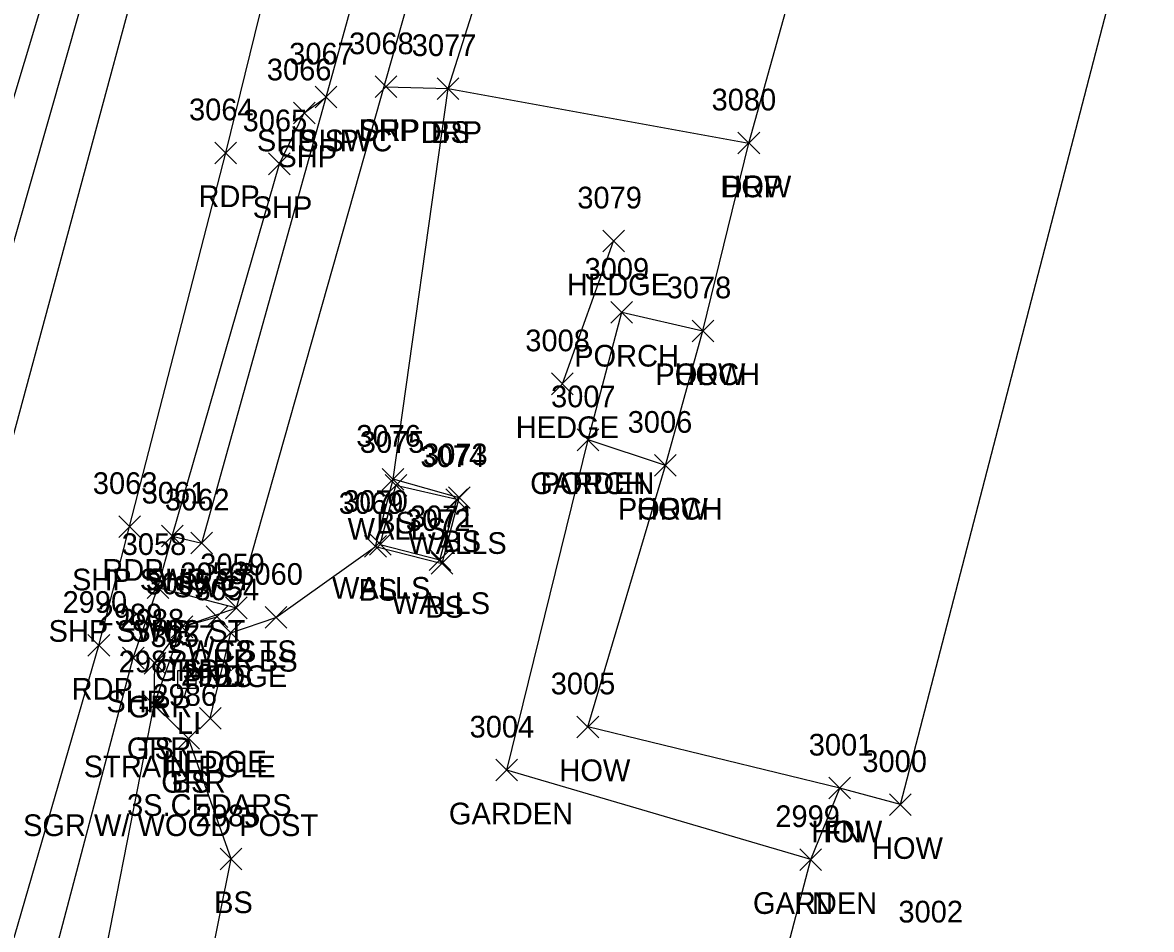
# Model space of a CAD drawing. Extents: x 1477930 to 1480780, y 774090 to 784647.
# Drawn here: x 1479566.7 to 1479670.7, y 775167.1 to 775250.7 of the extents above; entities that cross this region are included whole.
import ezdxf

# ---------------------------------------------------------------- set-up
doc = ezdxf.new("R2010")
doc.units = 0
for name, color, linetype in [('L_A', 7, 'Continuous'), ('L_C', 7, 'Continuous'), ('L_I', 7, 'Continuous'), ('L_TIC', 7, 'Continuous'), ('LAHR', 7, 'Continuous'), ('LAPB', 7, 'Continuous'), ('LBC', 7, 'Continuous'), ('LBF', 7, 'Continuous'), ('LELB', 7, 'Continuous'), ('LFNC', 7, 'Continuous'), ('LWS', 7, 'Continuous'), ('P_A', 7, 'Continuous'), ('P_I', 7, 'Continuous'), ('P_TIC', 7, 'Continuous'), ('PET', 7, 'Continuous'), ('PRC', 7, 'Continuous'), ('PSP', 7, 'Continuous'), ('R_A', 7, 'Continuous'), ('R_I', 7, 'Continuous'), ('R_TIC', 7, 'Continuous'), ('RDP', 7, 'Continuous'), ('RGR', 7, 'Continuous'), ('RSW', 7, 'Continuous'), ('U_A', 7, 'Continuous'), ('U_C', 7, 'Continuous'), ('U_I', 7, 'Continuous'), ('ULP', 7, 'Continuous')]:
    doc.layers.add(name, color=color, linetype=linetype)

msp = doc.modelspace()

# ---------------------------------------------------------------- linework, layer by layer
at = {"layer": 'L_TIC'}
for points in [[(1479604.91, 775243.6), (1479606.91, 775245.6)], [(1479606.91, 775243.6), (1479604.91, 775245.6)], [(1479632.62, 775238.59), (1479634.62, 775240.59)], [(1479634.62, 775238.59), (1479632.62, 775240.59)], [(1479620.16, 775229.56), (1479622.16, 775231.56)], [(1479622.16, 775229.56), (1479620.16, 775231.56)], [(1479620.91, 775222.99), (1479622.91, 775224.99)], [(1479622.91, 775222.99), (1479620.91, 775224.99)], [(1479628.39, 775221.28), (1479630.39, 775223.28)], [(1479630.39, 775221.28), (1479628.39, 775223.28)], [(1479628.39, 775221.28), (1479630.39, 775223.28)], [(1479630.39, 775221.28), (1479628.39, 775223.28)], [(1479615.45, 775216.4), (1479617.45, 775218.4)], [(1479617.45, 775216.4), (1479615.45, 775218.4)], [(1479617.81, 775211.24), (1479619.81, 775213.24)], [(1479619.81, 775211.24), (1479617.81, 775213.24)], [(1479617.81, 775211.24), (1479619.81, 775213.24)], [(1479619.81, 775211.24), (1479617.81, 775213.24)], [(1479624.93, 775208.89), (1479626.93, 775210.89)], [(1479626.93, 775208.89), (1479624.93, 775210.89)], [(1479624.93, 775208.89), (1479626.93, 775210.89)], [(1479626.93, 775208.89), (1479624.93, 775210.89)], [(1479599.85, 775207.61), (1479601.85, 775209.61)], [(1479601.85, 775207.61), (1479599.85, 775209.61)], [(1479599.85, 775207.61), (1479601.85, 775209.61)], [(1479601.85, 775207.61), (1479599.85, 775209.61)], [(1479600.11, 775207.04), (1479602.11, 775209.04)], [(1479602.11, 775207.04), (1479600.11, 775209.04)], [(1479600.11, 775207.04), (1479602.11, 775209.04)], [(1479602.11, 775207.04), (1479600.11, 775209.04)], [(1479605.71, 775205.73), (1479607.71, 775207.73)], [(1479607.71, 775205.73), (1479605.71, 775207.73)], [(1479605.94, 775205.9), (1479607.94, 775207.9)], [(1479607.94, 775205.9), (1479605.94, 775207.9)], [(1479598.23, 775201.42), (1479600.23, 775203.42)], [(1479600.23, 775201.42), (1479598.23, 775203.42)], [(1479598.23, 775201.42), (1479600.23, 775203.42)], [(1479600.23, 775201.42), (1479598.23, 775203.42)], [(1479598.67, 775201.6), (1479600.67, 775203.6)], [(1479600.67, 775201.6), (1479598.67, 775203.6)], [(1479598.67, 775201.6), (1479600.67, 775203.6)], [(1479600.67, 775201.6), (1479598.67, 775203.6)], [(1479604.17, 775200.19), (1479606.17, 775202.19)], [(1479606.17, 775200.19), (1479604.17, 775202.19)], [(1479604.36, 775199.85), (1479606.36, 775201.85)], [(1479606.36, 775199.85), (1479604.36, 775201.85)], [(1479585.42, 775195.76), (1479587.42, 775197.76)], [(1479587.42, 775195.76), (1479585.42, 775197.76)], [(1479589.06, 775194.88), (1479591.06, 775196.88)], [(1479591.06, 775194.88), (1479589.06, 775196.88)], [(1479580.4, 775194.01), (1479582.4, 775196.01)], [(1479582.4, 775194.01), (1479580.4, 775196.01)], [(1479584.89, 775193.46), (1479586.89, 775195.46)], [(1479586.89, 775193.46), (1479584.89, 775195.46)], [(1479584.89, 775193.46), (1479586.89, 775195.46)], [(1479586.89, 775193.46), (1479584.89, 775195.46)], [(1479577.83, 775186.82), (1479579.83, 775188.82)], [(1479579.83, 775186.82), (1479577.83, 775188.82)], [(1479583, 775185.59), (1479585, 775187.59)], [(1479585, 775185.59), (1479583, 775187.59)], [(1479617.79, 775184.79), (1479619.79, 775186.79)], [(1479619.79, 775184.79), (1479617.79, 775186.79)], [(1479581, 775183.73), (1479583, 775185.73)], [(1479583, 775183.73), (1479581, 775185.73)], [(1479610.32, 775180.81), (1479612.32, 775182.81)], [(1479612.32, 775180.81), (1479610.32, 775182.81)], [(1479640.99, 775179.15), (1479642.99, 775181.15)], [(1479642.99, 775179.15), (1479640.99, 775181.15)], [(1479640.99, 775179.15), (1479642.99, 775181.15)], [(1479642.99, 775179.15), (1479640.99, 775181.15)], [(1479646.59, 775177.63), (1479648.59, 775179.63)], [(1479648.59, 775177.63), (1479646.59, 775179.63)], [(1479646.59, 775177.63), (1479648.59, 775179.63)], [(1479648.59, 775177.63), (1479646.59, 775179.63)], [(1479584.92, 775172.63), (1479586.92, 775174.63)], [(1479586.92, 775172.63), (1479584.92, 775174.63)], [(1479638.33, 775172.56), (1479640.33, 775174.56)], [(1479640.33, 775172.56), (1479638.33, 775174.56)], [(1479638.33, 775172.56), (1479640.33, 775174.56)], [(1479640.33, 775172.56), (1479638.33, 775174.56)]]:
    msp.add_lwpolyline(points, dxfattribs=at)
at = {"layer": 'LAHR'}
for points in [[(1479616.45, 775217.4), (1479621.16, 775230.56)], [(1479584, 775186.59), (1479585.89, 775194.46)]]:
    msp.add_lwpolyline(points, dxfattribs=at)
at = {"layer": 'LAPB'}
msp.add_lwpolyline([(1479639.33, 775173.56), (1479611.32, 775181.81), (1479618.81, 775212.24)], dxfattribs=at)
at = {"layer": 'LBC'}
for points in [[(1479647.59, 775178.63), (1479641.99, 775180.15), (1479618.79, 775185.79), (1479625.93, 775209.89), (1479629.39, 775222.28), (1479633.62, 775239.59), (1479640.38, 775263.77), (1479667.82, 775256.6)], [(1479647.59, 775178.63), (1479667.82, 775256.6)]]:
    msp.add_lwpolyline(points, dxfattribs=at)
at = {"layer": 'LBF'}
msp.add_lwpolyline([(1479625.93, 775209.89), (1479618.81, 775212.24), (1479621.91, 775223.99), (1479629.39, 775222.28)], dxfattribs=at)
at = {"layer": 'LELB'}
for points in [[(1479585.89, 775194.46), (1479590.06, 775195.88), (1479599.23, 775202.42), (1479600.85, 775208.61), (1479605.91, 775244.6), (1479612.99, 775266.82), (1479623.15, 775296.78)], [(1479599.23, 775202.42), (1479605.36, 775200.85), (1479606.94, 775206.9), (1479600.85, 775208.61)], [(1479562.22, 775125.25), (1479572.92, 775157.6), (1479578.83, 775187.82), (1479581.4, 775195.01), (1479586.42, 775196.76)], [(1479495.75, 774910.51), (1479499.97, 774927.51), (1479504.38, 774948.16), (1479520.64, 774990.18), (1479525.58, 774996.15), (1479529.8, 774996.91), (1479531.37, 775007.34), (1479547.96, 775049.91), (1479566.92, 775099.68), (1479572.67, 775121.86), (1479581.47, 775151.49), (1479585.92, 775173.63), (1479582, 775184.73)]]:
    msp.add_lwpolyline(points, dxfattribs=at)
at = {"layer": 'LFNC'}
msp.add_lwpolyline([(1479670.71, 775144.89), (1479666.14, 775128.07), (1479629.86, 775137.61), (1479639.33, 775173.56), (1479641.99, 775180.15)], dxfattribs=at)
at = {"layer": 'LWS'}
for points in [[(1479599.67, 775202.6), (1479605.17, 775201.19), (1479606.71, 775206.73), (1479601.11, 775208.04)], [(1479599.67, 775202.6), (1479601.11, 775208.04)]]:
    msp.add_lwpolyline(points, dxfattribs=at)
at = {"layer": 'P_TIC'}
for points in [[(1479599.19, 775243.77), (1479601.19, 775245.77)], [(1479601.19, 775243.77), (1479599.19, 775245.77)], [(1479593.67, 775242.82), (1479595.67, 775244.82)], [(1479595.67, 775242.82), (1479593.67, 775244.82)], [(1479591.66, 775241.36), (1479593.66, 775243.36)], [(1479593.66, 775241.36), (1479591.66, 775243.36)], [(1479584.43, 775237.68), (1479586.43, 775239.68)], [(1479586.43, 775237.68), (1479584.43, 775239.68)], [(1479589.38, 775236.67), (1479591.38, 775238.67)], [(1479591.38, 775236.67), (1479589.38, 775238.67)], [(1479575.58, 775203.25), (1479577.58, 775205.25)], [(1479577.58, 775203.25), (1479575.58, 775205.25)], [(1479579.51, 775202.37), (1479581.51, 775204.37)], [(1479581.51, 775202.37), (1479579.51, 775204.37)], [(1479578.19, 775197.63), (1479580.19, 775199.63)], [(1479580.19, 775197.63), (1479578.19, 775199.63)], [(1479572.74, 775192.3), (1479574.74, 775194.3)], [(1479574.74, 775192.3), (1479572.74, 775194.3)], [(1479575.91, 775191.14), (1479577.91, 775193.14)], [(1479577.91, 775191.14), (1479575.91, 775193.14)]]:
    msp.add_lwpolyline(points, dxfattribs=at)
at = {"layer": 'PET'}
msp.add_lwpolyline([(1479231.31, 774636.06), (1479272.54, 774672.78), (1479302.99, 774702.6), (1479344.22, 774746.86), (1479373.44, 774780.01), (1479405.23, 774818.27), (1479428.23, 774848.68), (1479447.93, 774875.75), (1479460.71, 774894.51), (1479479.69, 774925.18), (1479480.31, 774927.38), (1479493.45, 774951.2), (1479514.74, 775006.53), (1479531.7, 775055.13), (1479548.14, 775106.72), (1479553.83, 775125.43), (1479564.45, 775161.29), (1479573.74, 775193.3), (1479576.58, 775204.25), (1479585.43, 775238.68), (1479593.96, 775273.34), (1479599.4, 775295.6)], dxfattribs=at)
at = {"layer": 'PRC'}
for points in [[(1479587.72, 775307.65), (1479575.01, 775262.49), (1479563.12, 775220.83), (1479548.57, 775168.37), (1479533.5, 775112.54), (1479513.76, 775053.7)], [(1479430.01, 774890.62), (1479468.91, 774957.83), (1479493.21, 775011.92), (1479503.06, 775052.08), (1479530.4, 775123.25), (1479541.54, 775166.06), (1479555.58, 775209.55), (1479571.78, 775263.31), (1479582.9, 775300.17)], [(1479438.76, 774885), (1479466.69, 774929.85), (1479479.06, 774955.89), (1479501.08, 775005.62), (1479520.94, 775059.64), (1479540.23, 775118.92), (1479552.22, 775163.96), (1479564.07, 775206.06), (1479578.9, 775260.88), (1479588.27, 775297.78)]]:
    msp.add_lwpolyline(points, dxfattribs=at)
at = {"layer": 'PSP'}
msp.add_lwpolyline([(1479441.63, 774858.96), (1479460.29, 774885.01), (1479481.52, 774912.36), (1479488.61, 774932.58), (1479495.59, 774950.17), (1479517.9, 775005.3), (1479535.63, 775053.88), (1479551.95, 775105.38), (1479558.13, 775123.89), (1479568.29, 775159.47), (1479576.91, 775192.14), (1479579.19, 775198.63), (1479580.51, 775203.37), (1479590.38, 775237.67), (1479592.66, 775242.36), (1479594.67, 775243.82)], dxfattribs=at)
at = {"layer": 'R_TIC'}
for points in [[(1479599.19, 775243.77), (1479601.19, 775245.77)], [(1479601.19, 775243.77), (1479599.19, 775245.77)], [(1479604.91, 775243.6), (1479606.91, 775245.6)], [(1479606.91, 775243.6), (1479604.91, 775245.6)], [(1479593.67, 775242.82), (1479595.67, 775244.82)], [(1479595.67, 775242.82), (1479593.67, 775244.82)], [(1479632.62, 775238.59), (1479634.62, 775240.59)], [(1479634.62, 775238.59), (1479632.62, 775240.59)], [(1479579.51, 775202.37), (1479581.51, 775204.37)], [(1479581.51, 775202.37), (1479579.51, 775204.37)], [(1479582.22, 775201.73), (1479584.22, 775203.73)], [(1479584.22, 775201.73), (1479582.22, 775203.73)], [(1479578.19, 775197.63), (1479580.19, 775199.63)], [(1479580.19, 775197.63), (1479578.19, 775199.63)], [(1479585.42, 775195.76), (1479587.42, 775197.76)], [(1479587.42, 775195.76), (1479585.42, 775197.76)], [(1479583.64, 775194.94), (1479585.64, 775196.94)], [(1479585.64, 775194.94), (1479583.64, 775196.94)], [(1479580.4, 775194.01), (1479582.4, 775196.01)], [(1479582.4, 775194.01), (1479580.4, 775196.01)], [(1479577.91, 775190.66), (1479579.91, 775192.66)], [(1479579.91, 775190.66), (1479577.91, 775192.66)], [(1479577.83, 775186.82), (1479579.83, 775188.82)], [(1479579.83, 775186.82), (1479577.83, 775188.82)], [(1479581, 775183.73), (1479583, 775185.73)], [(1479583, 775183.73), (1479581, 775185.73)]]:
    msp.add_lwpolyline(points, dxfattribs=at)
at = {"layer": 'RDP'}
msp.add_lwpolyline([(1479600.19, 775244.77), (1479605.91, 775244.6), (1479633.62, 775239.59)], dxfattribs=at)
at = {"layer": 'RGR'}
msp.add_lwpolyline([(1479582, 775184.73), (1479578.83, 775187.82), (1479578.91, 775191.66), (1479581.4, 775195.01), (1479584.64, 775195.94)], dxfattribs=at)
at = {"layer": 'RSW'}
for points in [[(1479580.51, 775203.37), (1479583.22, 775202.73), (1479594.67, 775243.82), (1479602.39, 775271.66), (1479608.81, 775294.92)], [(1479579.19, 775198.63), (1479586.42, 775196.76), (1479607.11, 775269.89), (1479613.43, 775293.13)]]:
    msp.add_lwpolyline(points, dxfattribs=at)
at = {"layer": 'ULP'}
for p, q in [((1479581.01, 775189.32), (1479581.01, 775190.98)), ((1479581.01, 775190.98), (1479582.68, 775190.98)), ((1479582.01, 775191.82), (1479581.84, 775190.98)), ((1479582.68, 775190.98), (1479582.68, 775189.32)), ((1479581.84, 775190.15), (1479581.84, 775190.15)), ((1479582.68, 775189.32), (1479581.01, 775189.32)), ((1479581.59, 775188.48), (1479581.84, 775189.32))]:
    msp.add_line(p, q, dxfattribs=at)

# ---------------------------------------------------------------- texts
at = {"layer": 'L_A'}
for s, p in [('BS', (1479604.35, 775239.6)), ('HOW', (1479631, 775234.59)), ('HEDGE', (1479616.86, 775225.56)), ('PORCH', (1479617.53, 775218.99)), ('PORCH', (1479625.01, 775217.28)), ('HOW', (1479626.77, 775217.28)), ('HEDGE', (1479612.15, 775212.4)), ('GARDEN', (1479613.48, 775207.24)), ('PORCH', (1479614.44, 775207.24)), ('PORCH', (1479621.55, 775204.89)), ('HOW', (1479623.32, 775204.89)), ('BS', (1479599.29, 775203.61)), ('BS', (1479599.29, 775203.61)), ('WALLS', (1479596.66, 775203.04)), ('WALLS', (1479596.66, 775203.04)), ('WALLS', (1479602.25, 775201.73)), ('BS', (1479605.39, 775201.9)), ('WALLS', (1479595.22, 775197.6)), ('WALLS', (1479595.22, 775197.6)), ('BS', (1479597.67, 775197.42)), ('BS', (1479597.67, 775197.42)), ('WALLS', (1479600.72, 775196.19)), ('BS', (1479603.8, 775195.85)), ('TS', (1479584.83, 775191.76)), ('TS', (1479579.81, 775190.01)), ('BS', (1479588.5, 775190.88)), ('HEDGE', (1479581.59, 775189.46)), ('BS', (1479584.33, 775189.46)), ('TS', (1479577.24, 775182.82)), ('HEDGE', (1479579.7, 775181.59)), ('HOW', (1479616.17, 775180.79)), ('BS', (1479580.44, 775179.73)), ('GARDEN', (1479605.99, 775176.81)), ('HOW', (1479639.38, 775175.15)), ('FN', (1479640.47, 775175.15)), ('HOW', (1479644.97, 775173.63)), ('HOW', (1479644.97, 775173.63)), ('BS', (1479584.36, 775168.63)), ('GARDEN', (1479634, 775168.56)), ('FN', (1479637.81, 775168.56))]:
    msp.add_text(s, height=2, dxfattribs=at).set_placement(p)
at = {"layer": 'L_C'}
for s, p in [('3S.CEDARS', (1479576.34, 775177.59)), ('SGR W/ WOOD POST', (1479566.76, 775175.73))]:
    msp.add_text(s, height=2, dxfattribs=at).set_placement(p)
at = {"layer": 'L_I'}
for s, p in [('3077', (1479602.57, 775247.6)), ('3080', (1479630.19, 775242.59)), ('3079', (1479617.82, 775233.56)), ('3009', (1479618.49, 775226.99)), ('3078', (1479626.05, 775225.28)), ('3078', (1479626.05, 775225.28)), ('3008', (1479613.03, 775220.4)), ('3007', (1479615.4, 775215.24)), ('3007', (1479615.4, 775215.24)), ('3006', (1479622.46, 775212.89)), ('3006', (1479622.46, 775212.89)), ('3076', (1479597.46, 775211.61)), ('3076', (1479597.46, 775211.61)), ('3075', (1479597.78, 775211.04)), ('3075', (1479597.78, 775211.04)), ('3074', (1479603.37, 775209.73)), ('3073', (1479603.61, 775209.9)), ('3070', (1479596.25, 775205.6)), ('3070', (1479596.25, 775205.6)), ('3069', (1479595.84, 775205.42)), ('3069', (1479595.84, 775205.42)), ('3072', (1479602.02, 775203.85)), ('3071', (1479602.4, 775204.19)), ('3059', (1479583.08, 775199.76)), ('3060', (1479586.59, 775198.88)), ('3055', (1479578.06, 775198.01)), ('3054', (1479582.55, 775197.46)), ('3054', (1479582.55, 775197.46)), ('2987', (1479575.57, 775190.82)), ('2991', (1479581.3, 775189.59)), ('3005', (1479615.37, 775188.79)), ('2986', (1479578.68, 775187.73)), ('3004', (1479607.9, 775184.81)), ('3001', (1479639.14, 775183.15)), ('3001', (1479639.14, 775183.15)), ('3000', (1479644.08, 775181.63)), ('3000', (1479644.08, 775181.63)), ('2985', (1479582.66, 775176.63)), ('2999', (1479636.06, 775176.56)), ('2999', (1479636.06, 775176.56)), ('3002', (1479647.4, 775167.77))]:
    msp.add_text(s, height=2, dxfattribs=at).set_placement(p)
at = {"layer": 'P_A'}
for s, p in [('SHP', (1479592.2, 775238.82)), ('SHP', (1479597.72, 775239.77)), ('SHP', (1479590.19, 775237.36)), ('RDP', (1479582.92, 775233.68)), ('SHP', (1479587.91, 775232.67)), ('RDP', (1479574.06, 775199.25)), ('SHP', (1479578.05, 775198.37)), ('SHP', (1479576.73, 775193.63)), ('RDP', (1479571.23, 775188.3)), ('SHP', (1479574.44, 775187.14))]:
    msp.add_text(s, height=2, dxfattribs=at).set_placement(p)
at = {"layer": 'P_I'}
for s, p in [('3068', (1479596.8, 775247.77)), ('3067', (1479591.28, 775246.82)), ('3066', (1479589.22, 775245.36)), ('3064', (1479582.05, 775241.68)), ('3065', (1479586.99, 775240.67)), ('3063', (1479573.19, 775207.25)), ('3061', (1479577.69, 775206.37)), ('3058', (1479575.85, 775201.63)), ('2990', (1479570.4, 775196.3)), ('2989', (1479573.64, 775195.14))]:
    msp.add_text(s, height=2, dxfattribs=at).set_placement(p)
at = {"layer": 'R_A'}
for s, p in [('SHP SWC', (1479588.3, 775238.82)), ('DRP', (1479597.68, 775239.77)), ('DRP', (1479603.4, 775239.6)), ('DRP', (1479631.11, 775234.59)), ('SHP SWC ST', (1479571.27, 775198.37)), ('SWC', (1479580.58, 775197.73)), ('SHP SWC2 ST', (1479569.11, 775193.63)), ('SWC2 TS', (1479580.08, 775191.76)), ('GRR', (1479582.13, 775190.94)), ('GRR', (1479578.89, 775190.01)), ('GRR', (1479576.4, 775186.66)), ('GRR', (1479576.32, 775182.82)), ('GRR', (1479579.49, 775179.73))]:
    msp.add_text(s, height=2, dxfattribs=at).set_placement(p)
at = {"layer": 'R_I'}
for s, p in [('3068', (1479596.8, 775247.77)), ('3077', (1479602.57, 775247.6)), ('3067', (1479591.28, 775246.82)), ('3080', (1479630.19, 775242.59)), ('3061', (1479577.69, 775206.37)), ('3062', (1479579.83, 775205.73)), ('3058', (1479575.85, 775201.63)), ('3059', (1479583.08, 775199.76)), ('3056', (1479581.24, 775198.94)), ('3055', (1479578.06, 775198.01)), ('2988', (1479575.65, 775194.66)), ('2987', (1479575.57, 775190.82)), ('2986', (1479578.68, 775187.73))]:
    msp.add_text(s, height=2, dxfattribs=at).set_placement(p)
at = {"layer": 'U_A'}
msp.add_text('LI', height=2, dxfattribs=at).set_placement((1479580.94, 775185.15))
at = {"layer": 'U_C'}
msp.add_text('STRAIN POLE', height=2, dxfattribs=at).set_placement((1479572.35, 775181.15))
at = {"layer": 'U_I'}
msp.add_text('3057', height=2, dxfattribs=at).set_placement((1479578.5, 775193.15))

doc.saveas('drawing.dxf')
